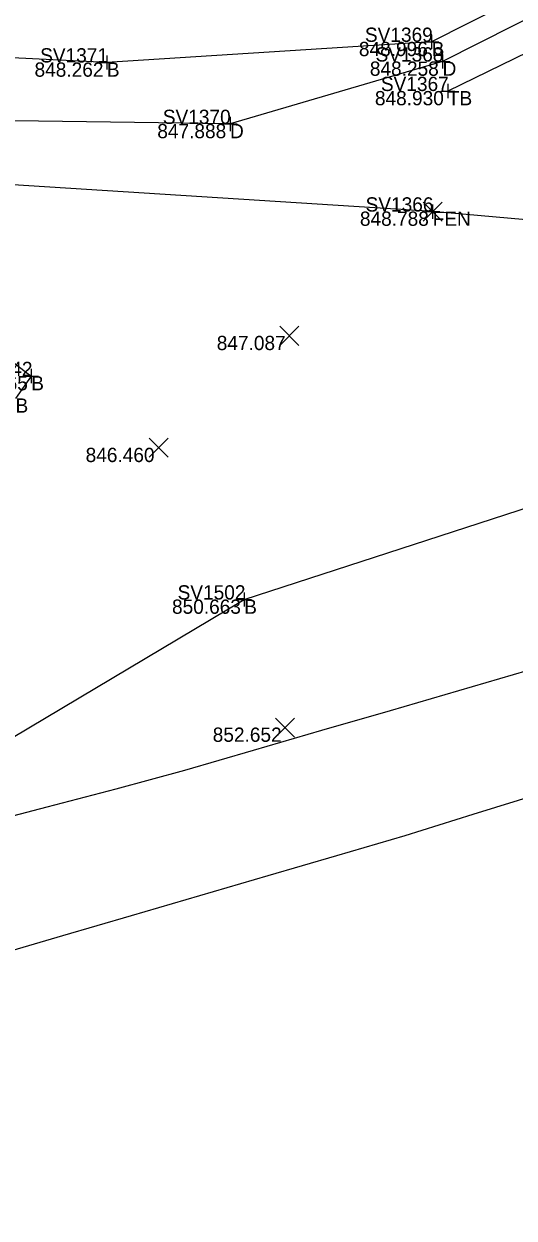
# Model space of a CAD drawing. Extents: x 2125299 to 2129212, y 713100 to 714300.
# Drawn here: x 2128381.6 to 2128416, y 713811.5 to 713895.2 of the extents above; entities that cross this region are included whole.
import ezdxf

# ---------------------------------------------------------------- set-up
doc = ezdxf.new("R2010")
doc.units = 0
for name, color, linetype in [('DR_X_Ditch', 7, 'Continuous'), ('DT_X_Terrain_Boundary', 7, 'Continuous'), ('PV_X_Field_Drive', 7, 'Continuous'), ('RD_X_Fence', 7, 'Continuous'), ('RW_P_Esmt_TMP', 7, 'Continuous'), ('RW_X_Esmt_CH', 7, 'Continuous'), ('RW_X_Fee_WL', 7, 'Continuous'), ('SV_X_Break_Lines', 7, 'Continuous'), ('SV_X_Mon_Cells_Found', 7, 'Continuous'), ('SV_X_Text_Elevation', 7, 'Continuous'), ('SV_X_Top_of_Bank', 7, 'Continuous')]:
    doc.layers.add(name, color=color, linetype=linetype)

msp = doc.modelspace()

# ---------------------------------------------------------------- linework, layer by layer
at = {"layer": 'DR_X_Ditch'}
msp.add_lwpolyline([(2128604.481, 713972.859), (2128563.259, 713957.895), (2128524.583, 713946.255), (2128524.597, 713946.253), (2128472.88, 713922.441), (2128453.797, 713914.261), (2128410.953, 713892.601), (2128396.045, 713888.223), (2128367.499, 713888.623)], dxfattribs=at)
at = {"layer": 'DT_X_Terrain_Boundary'}
msp.add_lwpolyline([(2128312.004, 713811.488), (2128316.836, 713812.774), (2128321.668, 713814.059), (2128326.499, 713815.345), (2128331.331, 713816.631), (2128336.163, 713817.916), (2128340.995, 713819.202), (2128345.827, 713820.488), (2128350.659, 713821.773), (2128355.491, 713823.059), (2128360.323, 713824.345), (2128365.13, 713825.717), (2128369.93, 713827.117), (2128374.73, 713828.517), (2128379.53, 713829.917), (2128384.33, 713831.317), (2128389.13, 713832.717), (2128393.93, 713834.117), (2128398.73, 713835.517), (2128403.53, 713836.917), (2128408.33, 713838.319), (2128413.103, 713839.808), (2128417.876, 713841.297)], dxfattribs=at)
at = {"layer": 'PV_X_Field_Drive'}
for points in [[(2128311.329, 713819.435), (2128316.156, 713820.739), (2128320.983, 713822.043), (2128325.81, 713823.347), (2128330.637, 713824.65), (2128335.464, 713825.954), (2128340.291, 713827.258), (2128345.118, 713828.562), (2128349.945, 713829.866), (2128354.764, 713831.199), (2128359.574, 713832.563), (2128364.384, 713833.928), (2128368.878, 713836.103), (2128373.552, 713837.799), (2128378.388, 713839.07), (2128383.224, 713840.339), (2128388.062, 713841.604), (2128392.887, 713842.912), (2128397.688, 713844.308), (2128402.49, 713845.703), (2128407.291, 713847.099), (2128412.092, 713848.494), (2128416.894, 713849.89)], [(2128312.004, 713811.488), (2128316.836, 713812.774), (2128321.668, 713814.059), (2128326.499, 713815.345), (2128331.331, 713816.631), (2128336.163, 713817.916), (2128340.995, 713819.202), (2128345.827, 713820.488), (2128350.659, 713821.773), (2128355.491, 713823.059), (2128360.323, 713824.345), (2128365.13, 713825.717), (2128369.93, 713827.117), (2128374.73, 713828.517), (2128379.53, 713829.917), (2128384.33, 713831.317), (2128389.13, 713832.717), (2128393.93, 713834.117), (2128398.73, 713835.517), (2128403.53, 713836.917), (2128408.33, 713838.319), (2128413.103, 713839.808), (2128417.876, 713841.297)]]:
    msp.add_lwpolyline(points, dxfattribs=at)
at = {"layer": 'RD_X_Fence'}
msp.add_lwpolyline([(2128620.57, 713921.414), (2128582.003, 713911.258), (2128527.9, 713897.049), (2128485.218, 713885.694), (2128444.136, 713879.079), (2128410.256, 713882.079), (2128351.04, 713885.853)], dxfattribs=at)
at = {"layer": 'SV_X_Break_Lines'}
for points in [[(2128473.365, 713923.912), (2128453.453, 713915.843), (2128410.188, 713893.98), (2128387.409, 713892.535), (2128363.211, 713893.719), (2128345.595, 713896.5), (2128318.819, 713891.258), (2128295.116, 713880.906), (2128274.488, 713885.799), (2128242.12, 713879.196), (2128218.829, 713874.939), (2128184.367, 713862.099), (2128151.548, 713852.787), (2128121.592, 713848.655), (2128121.634, 713848.486), (2128085.287, 713843.491), (2128066.442, 713838.356)], [(2128379.904, 713872.221), (2128382.103, 713870.541), (2128381.002, 713868.975)], [(2128285.007, 713846.966), (2128304.036, 713841.037), (2128326.028, 713831.967), (2128335.229, 713829.953), (2128351.209, 713834.175), (2128372.654, 713840.365), (2128397.041, 713854.87), (2128424.528, 713863.803), (2128437.965, 713867.069)]]:
    msp.add_lwpolyline(points, dxfattribs=at)
at = {"layer": 'SV_X_Mon_Cells_Found'}
for p, q in [((2128410.188, 713894.48), (2128410.188, 713893.48)), ((2128409.688, 713893.98), (2128410.688, 713893.98)), ((2128410.188, 713893.98), (2128410.188, 713893.98)), ((2128387.409, 713893.035), (2128387.409, 713892.035)), ((2128410.953, 713893.101), (2128410.953, 713892.101)), ((2128386.909, 713892.535), (2128387.909, 713892.535)), ((2128387.409, 713892.535), (2128387.409, 713892.535)), ((2128410.453, 713892.601), (2128411.453, 713892.601)), ((2128410.953, 713892.601), (2128410.953, 713892.601)), ((2128410.822, 713890.532), (2128411.822, 713890.532)), ((2128411.322, 713891.032), (2128411.322, 713890.032)), ((2128411.322, 713890.532), (2128411.322, 713890.532)), ((2128396.045, 713888.723), (2128396.045, 713887.723)), ((2128395.545, 713888.223), (2128396.545, 713888.223)), ((2128396.045, 713888.223), (2128396.045, 713888.223)), ((2128409.756, 713882.079), (2128410.756, 713882.079)), ((2128410.256, 713882.579), (2128410.256, 713881.579)), ((2128410.256, 713882.079), (2128410.256, 713882.079)), ((2128382.103, 713871.041), (2128382.103, 713870.041)), ((2128381.603, 713870.541), (2128382.603, 713870.541)), ((2128382.103, 713870.541), (2128382.103, 713870.541)), ((2128397.041, 713855.37), (2128397.041, 713854.37)), ((2128396.541, 713854.87), (2128397.541, 713854.87)), ((2128397.041, 713854.87), (2128397.041, 713854.87))]:
    msp.add_line(p, q, dxfattribs=at)
at = {"layer": 'SV_X_Text_Elevation'}
for p, q in [((2128409.589, 713881.412), (2128410.923, 713882.747)), ((2128409.589, 713882.747), (2128410.923, 713881.412)), ((2128399.545, 713872.695), (2128400.879, 713874.03)), ((2128399.545, 713874.03), (2128400.879, 713872.695)), ((2128390.365, 713864.844), (2128391.699, 713866.179)), ((2128390.365, 713866.179), (2128391.699, 713864.844)), ((2128399.238, 713845.223), (2128400.572, 713846.558)), ((2128399.238, 713846.558), (2128400.572, 713845.223))]:
    msp.add_line(p, q, dxfattribs=at)
at = {"layer": 'SV_X_Top_of_Bank'}
msp.add_lwpolyline([(2128609.034, 713957.299), (2128567.95, 713948.54), (2128527.006, 713933.342), (2128474.233, 713917.806), (2128454.285, 713911.498), (2128411.322, 713890.532)], dxfattribs=at)

# ---------------------------------------------------------------- texts
at = {"layer": 'RW_P_Esmt_TMP'}
for s, p in [('B', (2128410.188, 713892.98)), ('B', (2128387.409, 713891.535)), ('D', (2128410.953, 713891.601)), ('TB', (2128411.322, 713889.532)), ('D', (2128396.045, 713887.223)), ('FEN', (2128410.256, 713881.079)), ('B', (2128382.103, 713869.541)), ('B', (2128381.002, 713867.975)), ('B', (2128397.041, 713853.87))]:
    msp.add_text(s, height=1, dxfattribs=at).set_placement(p)
at = {"layer": 'RW_X_Esmt_CH'}
for s, p in [('SV1369', (2128405.506, 713893.98)), ('SV1371', (2128382.729, 713892.535)), ('SV1368', (2128406.254, 713892.601)), ('SV1367', (2128406.628, 713890.532)), ('SV1370', (2128391.333, 713888.223)), ('SV1366', (2128405.554, 713882.079)), ('SV1442', (2128377.432, 713870.541)), ('SV1502', (2128392.37, 713854.87))]:
    msp.add_text(s, height=1, dxfattribs=at).set_placement(p)
at = {"layer": 'RW_X_Fee_WL'}
for s, p in [('848.996', (2128405.084, 713892.98)), ('848.262', (2128382.336, 713891.535)), ('848.258', (2128405.853, 713891.601)), ('848.930', (2128406.208, 713889.532)), ('847.888', (2128390.945, 713887.223)), ('848.788', (2128405.156, 713881.079)), ('848.788', (2128405.156, 713881.079)), ('847.087', (2128395.116, 713872.363)), ('845.765', (2128377.033, 713869.541)), ('846.460', (2128385.918, 713864.511)), ('850.663', (2128391.977, 713853.87)), ('852.652', (2128394.832, 713844.891))]:
    msp.add_text(s, height=1, dxfattribs=at).set_placement(p)

doc.saveas('drawing.dxf')
